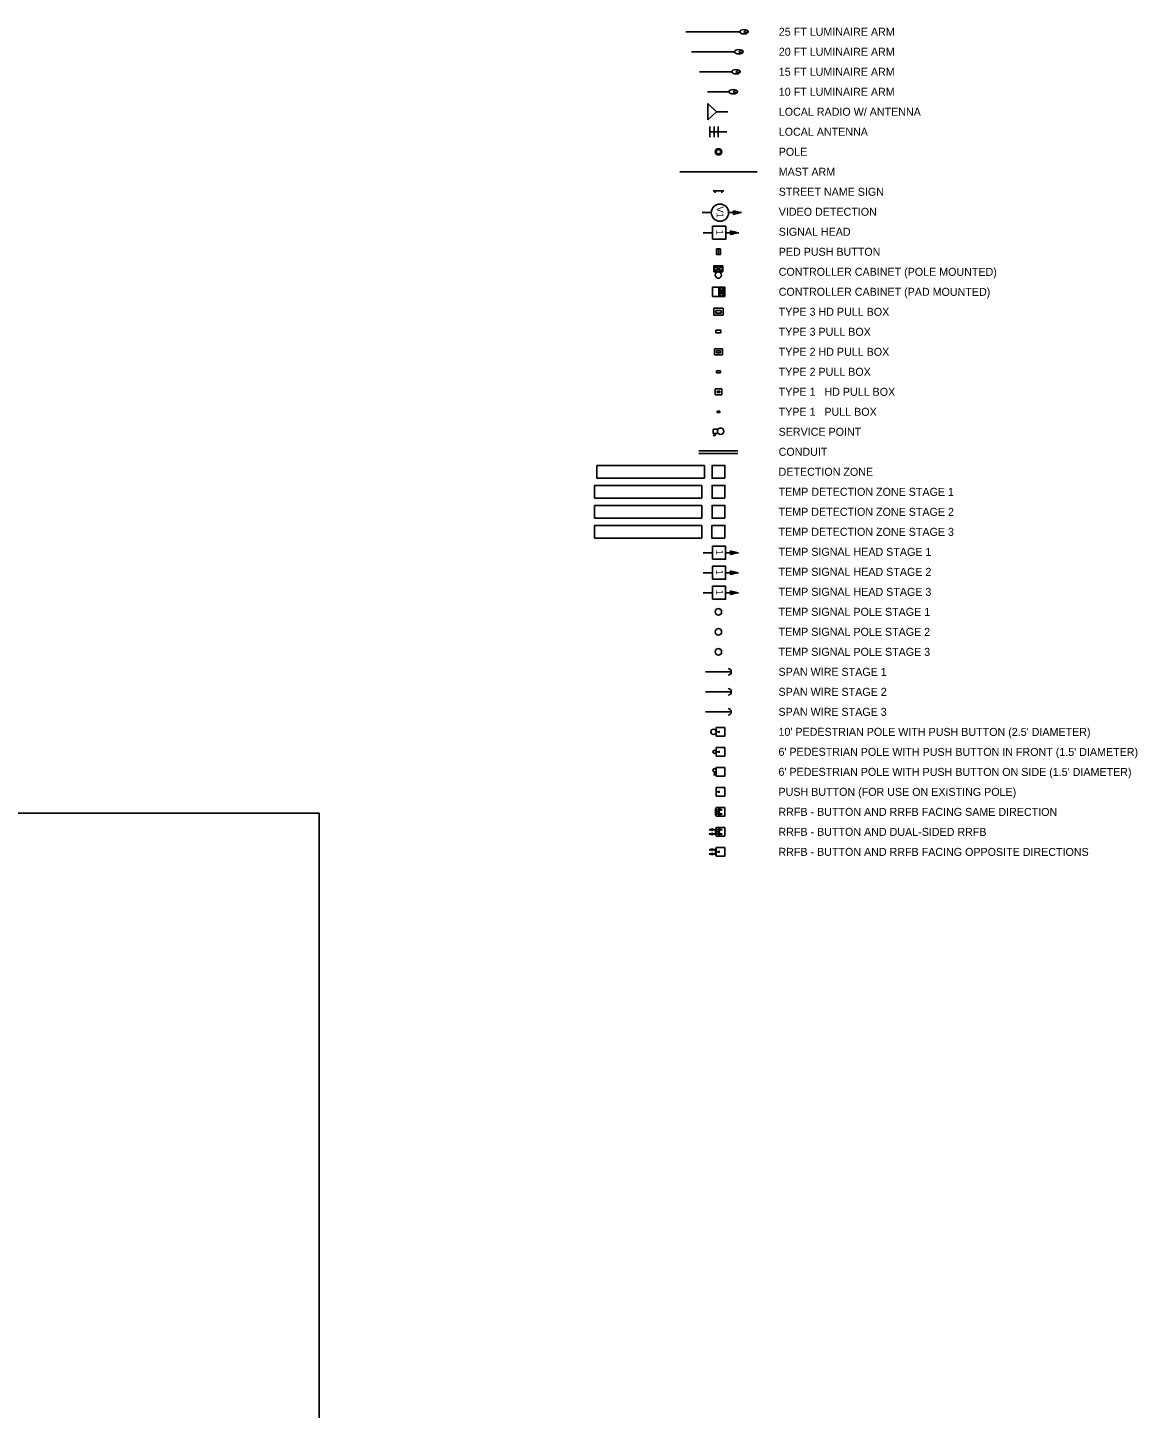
# Model space of a CAD drawing. Extents: x 991933 to 997296, y 1973751 to 1976728.
# Drawn here: x 993434 to 993950, y 1976002 to 1976644 of the extents above; entities that cross this region are included whole.
import ezdxf

# ---------------------------------------------------------------- set-up
doc = ezdxf.new("R2010")
doc.units = 0
for name, color, linetype in [('_CIVIL_CONSTRUCTION', 7, 'Continuous'), ('DSN_RDWY_Alignment Annotation', 7, 'Continuous'), ('DSN_ROW_Line-Annotation', 7, 'Continuous'), ('DSN_ROW_Point', 7, 'Continuous'), ('EX_ALIGNMENT', 7, 'Continuous'), ('EX_ROW', 7, 'Continuous'), ('EX_ROW_Annotation', 7, 'Continuous'), ('Level 23', 7, 'Continuous'), ('S_CROSS_DRAIN', 7, 'Continuous'), ('S_CURB', 7, 'Continuous'), ('S_DRIVEWAY', 7, 'Continuous'), ('S_DROP_INLET', 7, 'Continuous'), ('S_HWY_SYMBOLS', 7, 'Continuous'), ('S_HWY_TEXT', 7, 'Continuous'), ('S_ORTHO_IMAGE', 7, 'Continuous'), ('S_PARKING', 7, 'Continuous'), ('S_PAVEMENT_CROWN', 7, 'Continuous'), ('S_SHOULDER', 7, 'Continuous'), ('S_SIDEWALK', 7, 'Continuous'), ('S_WALL', 7, 'Continuous'), ('S_WALL_ANNOT', 7, 'Continuous')]:
    doc.layers.add(name, color=color, linetype=linetype)

msp = doc.modelspace()

# ---------------------------------------------------------------- linework, layer by layer
at = {"layer": '_CIVIL_CONSTRUCTION'}
for p, q in [((993697.45, 1976422.15), (993747.45, 1976422.15)), ((993697.45, 1976416.15), (993697.45, 1976422.15)), ((993747.45, 1976422.15), (993747.45, 1976416.15)), ((993747.45, 1976416.15), (993697.45, 1976416.15))]:
    msp.add_line(p, q, dxfattribs=at)
msp.add_lwpolyline([(993758.13, 1976416.15), (993752.13, 1976416.15), (993752.13, 1976422.15), (993758.13, 1976422.15)], close=True, dxfattribs=at)
at = {"layer": 'DSN_RDWY_Alignment Annotation'}
for p, q in [((993758.42, 1976400.1), (993764.46, 1976400.1)), ((993748.01, 1976400.08), (993752.35, 1976400.08))]:
    msp.add_line(p, q, dxfattribs=at)
msp.add_lwpolyline([(993752.35, 1976397.06), (993752.35, 1976403.12), (993758.42, 1976403.12), (993758.42, 1976397.06)], close=True, dxfattribs=at)
for centre, radius, start, end in [((993759.19, 1976400.1), 1.63, 328.15268, 31.84732), ((993768.87, 1976429.24), 29.47, 253.65357, 261.39168), ((993768.87, 1976370.96), 29.47, 98.60832, 106.34643)]:
    msp.add_arc(centre, radius, start, end, dxfattribs=at)
at = {"layer": 'DSN_ROW_Line-Annotation'}
msp.add_line((993761.08, 1976326.15), (993749.08, 1976326.15), dxfattribs=at)
msp.add_circle((993755.09, 1976354.05), 1.5, dxfattribs=at)
msp.add_arc((993759.58, 1976326.15), 1.5, 270, 90, dxfattribs=at)
at = {"layer": 'DSN_ROW_Point'}
for p, q in [((993748, 1976390.78), (993752.35, 1976390.78)), ((993758.41, 1976390.8), (993764.45, 1976390.8))]:
    msp.add_line(p, q, dxfattribs=at)
msp.add_lwpolyline([(993752.35, 1976387.76), (993752.35, 1976393.82), (993758.41, 1976393.82), (993758.41, 1976387.76)], close=True, dxfattribs=at)
for centre, radius, start, end in [((993759.19, 1976390.8), 1.63, 328.15268, 31.84732), ((993768.87, 1976419.94), 29.47, 253.65357, 261.39168), ((993768.87, 1976361.66), 29.47, 98.60832, 106.34643)]:
    msp.add_arc(centre, radius, start, end, dxfattribs=at)
at = {"layer": 'EX_ALIGNMENT'}
msp.add_line((993761.09, 1976335.45), (993749.09, 1976335.45), dxfattribs=at)
msp.add_circle((993755.1, 1976363.35), 1.5, dxfattribs=at)
msp.add_arc((993759.59, 1976335.45), 1.5, 270, 90, dxfattribs=at)
at = {"layer": 'EX_ROW'}
for p, q in [((993697.45, 1976412.85), (993747.45, 1976412.85)), ((993697.45, 1976406.85), (993697.45, 1976412.85)), ((993747.45, 1976406.85), (993697.45, 1976406.85)), ((993747.45, 1976412.85), (993747.45, 1976406.85))]:
    msp.add_line(p, q, dxfattribs=at)
msp.add_lwpolyline([(993758.12, 1976406.85), (993752.12, 1976406.85), (993752.12, 1976412.85), (993758.12, 1976412.85)], close=True, dxfattribs=at)
at = {"layer": 'EX_ROW_Annotation'}
for p, q in [((993748, 1976381.48), (993752.35, 1976381.48)), ((993758.41, 1976381.5), (993764.45, 1976381.5))]:
    msp.add_line(p, q, dxfattribs=at)
msp.add_lwpolyline([(993752.35, 1976378.46), (993752.35, 1976384.52), (993758.41, 1976384.52), (993758.41, 1976378.46)], close=True, dxfattribs=at)
for centre, radius, start, end in [((993759.18, 1976381.5), 1.63, 328.15268, 31.84732), ((993768.86, 1976410.64), 29.47, 253.65357, 261.39168), ((993768.86, 1976352.36), 29.47, 98.60832, 106.34643)]:
    msp.add_arc(centre, radius, start, end, dxfattribs=at)
at = {"layer": 'Level 23'}
msp.add_lwpolyline([(992579.43, 1975649.05), (993569.43, 1975649.05), (993569.43, 1976279.05), (992579.43, 1976279.05)], close=True, dxfattribs=at)
at = {"layer": 'S_CROSS_DRAIN'}
for p, q in [((993757.64, 1976568.45), (993752.64, 1976568.45)), ((993753.64, 1976567.45), (993753.64, 1976568.45)), ((993756.64, 1976568.45), (993756.64, 1976567.45)), ((993757.64, 1976568.45), (993756.64, 1976568.45))]:
    msp.add_line(p, q, dxfattribs=at)
at = {"layer": 'S_CURB'}
for p, q in [((993737.14, 1976577.25), (993773.14, 1976577.25)), ((993753.82, 1976281.15), (993753.82, 1976278.15)), ((993753.82, 1976280.65), (993756.84, 1976280.65)), ((993753.82, 1976279.77), (993753.82, 1976279.52)), ((993753.82, 1976279.77), (993754.07, 1976279.77)), ((993754.07, 1976279.52), (993753.82, 1976279.52)), ((993753.82, 1976278.65), (993756.84, 1976278.65)), ((993754.07, 1976279.52), (993754.07, 1976279.77)), ((993753.81, 1976271.85), (993753.81, 1976268.85)), ((993753.81, 1976271.35), (993750.79, 1976271.35)), ((993753.81, 1976269.35), (993750.79, 1976269.35)), ((993753.81, 1976271.35), (993756.83, 1976271.35)), ((993753.81, 1976270.47), (993753.81, 1976270.22)), ((993753.81, 1976270.47), (993754.06, 1976270.47)), ((993754.06, 1976270.22), (993753.81, 1976270.22)), ((993753.81, 1976269.35), (993756.83, 1976269.35)), ((993754.06, 1976270.22), (993754.06, 1976270.47)), ((993753.81, 1976262.05), (993750.79, 1976262.05)), ((993753.81, 1976260.05), (993750.79, 1976260.05)), ((993753.81, 1976262.55), (993753.81, 1976259.55)), ((993753.81, 1976261.17), (993753.81, 1976260.92)), ((993753.81, 1976261.17), (993754.06, 1976261.17)), ((993754.06, 1976260.92), (993753.81, 1976260.92)), ((993754.06, 1976260.92), (993754.06, 1976261.17))]:
    msp.add_line(p, q, dxfattribs=at)
for centre, radius in [((993755.14, 1976586.55), 1.5), ((993755.14, 1976586.55), 1.25), ((993755.14, 1976586.55), 1), ((993755.1, 1976372.65), 1.5), ((993752.83, 1976316.85), 1.25), ((993753.33, 1976307.55), 0.75), ((993753.33, 1976299), 0.75)]:
    msp.add_circle(centre, radius, dxfattribs=at)
for centre, radius, start, end in [((993754.2, 1976280.65), 0.814, 328.15268, 31.84732), ((993759.04, 1976295.22), 14.74, 253.65357, 261.39168), ((993759.04, 1976266.08), 14.74, 98.60832, 106.34643), ((993754.2, 1976278.65), 0.814, 328.15268, 31.84732), ((993759.04, 1976293.22), 14.74, 253.65357, 261.39168), ((993759.04, 1976264.08), 14.74, 98.60832, 106.34643), ((993748.59, 1976285.92), 14.74, 278.60832, 286.34643), ((993753.43, 1976271.35), 0.814, 148.15268, 211.84732), ((993754.2, 1976271.35), 0.814, 328.15268, 31.84732), ((993759.04, 1976285.92), 14.74, 253.65357, 261.39168), ((993748.59, 1976256.78), 14.74, 73.65357, 81.39168), ((993748.59, 1976283.92), 14.74, 278.60832, 286.34643), ((993748.59, 1976254.78), 14.74, 73.65357, 81.39168), ((993753.43, 1976269.35), 0.814, 148.15268, 211.84732), ((993759.04, 1976256.78), 14.74, 98.60832, 106.34643), ((993754.2, 1976269.35), 0.814, 328.15268, 31.84732), ((993759.04, 1976283.92), 14.74, 253.65357, 261.39168), ((993759.04, 1976254.78), 14.74, 98.60832, 106.34643), ((993748.58, 1976276.62), 14.74, 278.60832, 286.34643), ((993748.58, 1976247.48), 14.74, 73.65357, 81.39168), ((993748.58, 1976274.62), 14.74, 278.60832, 286.34643), ((993748.58, 1976245.48), 14.74, 73.65357, 81.39168), ((993753.42, 1976262.05), 0.814, 148.15268, 211.84732), ((993753.42, 1976260.05), 0.814, 148.15268, 211.84732)]:
    msp.add_arc(centre, radius, start, end, dxfattribs=at)
at = {"layer": 'S_DRIVEWAY'}
for p, q in [((993757.31, 1976513.78), (993752.98, 1976513.78)), ((993752.98, 1976513.78), (993752.98, 1976510.51)), ((993752.98, 1976510.51), (993757.31, 1976510.51)), ((993753.98, 1976512.78), (993753.98, 1976511.51)), ((993756.31, 1976512.78), (993753.98, 1976512.78)), ((993753.98, 1976511.51), (993756.31, 1976511.51)), ((993756.31, 1976511.51), (993756.31, 1976512.78)), ((993757.31, 1976510.51), (993757.31, 1976513.78)), ((993753.97, 1976503.66), (993753.97, 1976502.39)), ((993756.3, 1976503.66), (993753.97, 1976503.66)), ((993756.3, 1976502.39), (993756.3, 1976503.66)), ((993753.97, 1976502.39), (993756.3, 1976502.39)), ((993757.01, 1976495), (993753.26, 1976495)), ((993753.26, 1976495), (993753.26, 1976492.08)), ((993753.26, 1976492.08), (993757.01, 1976492.08)), ((993754.26, 1976493.08), (993754.26, 1976494)), ((993754.26, 1976494), (993756.01, 1976494)), ((993754.26, 1976494), (993754.26, 1976493.08)), ((993756.01, 1976494), (993754.26, 1976494)), ((993754.26, 1976493.08), (993756.01, 1976493.08)), ((993754.26, 1976493.08), (993756.01, 1976493.08)), ((993756.01, 1976493.08), (993756.01, 1976494)), ((993756.01, 1976493.08), (993756.01, 1976494)), ((993757.01, 1976492.08), (993757.01, 1976495)), ((993754.26, 1976484.71), (993754.26, 1976483.79)), ((993756.01, 1976484.71), (993754.26, 1976484.71)), ((993754.26, 1976483.79), (993756.01, 1976483.79)), ((993756.01, 1976483.79), (993756.01, 1976484.71)), ((993754.08, 1976316.85), (993755.4, 1976316.85)), ((993755.4, 1976316.41), (993755.4, 1976317.28)), ((993754.08, 1976307.55), (993755.4, 1976307.55)), ((993755.4, 1976307.11), (993755.4, 1976307.98)), ((993753.33, 1976298.25), (993753.33, 1976296.93)), ((993752.89, 1976296.93), (993753.76, 1976296.93)), ((993754.07, 1976288.95), (993755.39, 1976288.95)), ((993755.39, 1976288.51), (993755.39, 1976289.38)), ((993754.07, 1976279.65), (993755.39, 1976279.65)), ((993755.38, 1976279.21), (993755.39, 1976280.08)), ((993754.06, 1976270.35), (993755.38, 1976270.35)), ((993755.38, 1976269.91), (993755.38, 1976270.78)), ((993754.06, 1976261.05), (993755.38, 1976261.05)), ((993755.38, 1976260.61), (993755.38, 1976261.48))]:
    msp.add_line(p, q, dxfattribs=at)
msp.add_lwpolyline([(993754.28, 1976538.73), (993756.02, 1976538.73), (993756.02, 1976541.36), (993754.28, 1976541.36)], close=True, dxfattribs=at)
at = {"layer": 'S_DROP_INLET'}
for points in [[(993754.08, 1976318.85), (993758.08, 1976318.85), (993758.08, 1976314.85), (993754.08, 1976314.85)], [(993754.08, 1976309.55), (993758.08, 1976309.55), (993758.08, 1976305.55), (993754.08, 1976305.55)], [(993754.08, 1976300.25), (993758.08, 1976300.25), (993758.08, 1976296.25), (993754.08, 1976296.25)], [(993754.07, 1976290.95), (993758.07, 1976290.95), (993758.07, 1976286.95), (993754.07, 1976286.95)], [(993754.07, 1976281.65), (993758.07, 1976281.65), (993758.07, 1976277.65), (993754.07, 1976277.65)], [(993754.06, 1976272.35), (993758.06, 1976272.35), (993758.06, 1976268.35), (993754.06, 1976268.35)], [(993754.06, 1976263.05), (993758.06, 1976263.05), (993758.06, 1976259.05), (993754.06, 1976259.05)]]:
    msp.add_lwpolyline(points, close=True, dxfattribs=at)
at = {"layer": 'S_HWY_SYMBOLS'}
for p, q in [((993697.46, 1976431.45), (993747.46, 1976431.45)), ((993697.46, 1976425.45), (993697.46, 1976431.45)), ((993747.46, 1976431.45), (993747.46, 1976425.45)), ((993747.46, 1976425.45), (993697.46, 1976425.45))]:
    msp.add_line(p, q, dxfattribs=at)
msp.add_lwpolyline([(993758.13, 1976425.45), (993752.13, 1976425.45), (993752.13, 1976431.45), (993758.13, 1976431.45)], close=True, dxfattribs=at)
at = {"layer": 'S_HWY_TEXT'}
msp.add_line((993761.09, 1976344.75), (993749.09, 1976344.75), dxfattribs=at)
msp.add_arc((993759.59, 1976344.75), 1.5, 270, 90, dxfattribs=at)
at = {"layer": 'S_PARKING'}
for p, q in [((993752.63, 1976457.6), (993752.63, 1976455.6)), ((993752.63, 1976457.6), (993754.63, 1976457.6)), ((993752.63, 1976455.6), (993754.63, 1976455.6)), ((993752.63, 1976454.6), (993753.63, 1976454.6)), ((993753.63, 1976455.6), (993753.63, 1976454.6)), ((993754.63, 1976457.6), (993754.63, 1976455.6)), ((993746.06, 1976447.54), (993764.19, 1976447.54)), ((993746.06, 1976446.22), (993764.19, 1976446.22))]:
    msp.add_line(p, q, dxfattribs=at)
msp.add_circle((993756.13, 1976456.6), 1.5, dxfattribs=at)
at = {"layer": 'S_PAVEMENT_CROWN'}
for p, q in [((993752.28, 1976523.61), (993758.02, 1976523.61)), ((993752.28, 1976523.61), (993752.28, 1976519.28)), ((993755.28, 1976523.61), (993755.28, 1976519.28)), ((993755.61, 1976523.28), (993755.61, 1976519.61)), ((993757.69, 1976519.61), (993755.61, 1976523.28)), ((993755.61, 1976523.28), (993757.69, 1976523.28)), ((993757.69, 1976523.26), (993755.61, 1976519.61)), ((993757.69, 1976523.28), (993757.69, 1976519.61)), ((993758.02, 1976523.61), (993758.02, 1976519.28)), ((993752.28, 1976519.28), (993758.02, 1976519.28)), ((993755.61, 1976519.61), (993757.69, 1976519.61))]:
    msp.add_line(p, q, dxfattribs=at)
at = {"layer": 'S_SHOULDER'}
for p, q in [((993740, 1976642.34), (993765, 1976642.34)), ((993742.59, 1976633.04), (993762.59, 1976633.04)), ((993746.29, 1976623.74), (993761.29, 1976623.74)), ((993750.02, 1976614.44), (993760.02, 1976614.44)), ((993750.14, 1976601.43), (993750.14, 1976608.93)), ((993750.14, 1976608.93), (993754.14, 1976605.18)), ((993754.14, 1976605.18), (993750.14, 1976601.43)), ((993759.49, 1976605.18), (993754.14, 1976605.18)), ((993751.06, 1976598.34), (993751.06, 1976593.34)), ((993751.06, 1976595.84), (993759.06, 1976595.84)), ((993753.06, 1976598.34), (993753.06, 1976593.34)), ((993755.06, 1976598.34), (993755.06, 1976593.34)), ((993752.9, 1976530.73), (993752.9, 1976533.47)), ((993752.9, 1976533.47), (993757.23, 1976533.47)), ((993752.9, 1976530.73), (993757.23, 1976530.73)), ((993753.23, 1976533.14), (993756.9, 1976533.14)), ((993753.23, 1976531.06), (993753.23, 1976533.14)), ((993756.9, 1976533.14), (993753.23, 1976531.06)), ((993753.23, 1976531.06), (993756.9, 1976531.06)), ((993753.25, 1976533.14), (993756.9, 1976531.06)), ((993756.9, 1976531.06), (993756.9, 1976533.14)), ((993757.23, 1976530.73), (993757.23, 1976533.47)), ((993753.54, 1976476.31), (993756.73, 1976476.31)), ((993753.54, 1976473.58), (993753.54, 1976476.31)), ((993753.54, 1976473.58), (993756.73, 1976473.58)), ((993754.54, 1976474.58), (993754.54, 1976475.31)), ((993754.54, 1976475.31), (993755.73, 1976475.31)), ((993754.54, 1976474.58), (993755.73, 1976474.58)), ((993755.73, 1976474.58), (993755.73, 1976475.31)), ((993756.73, 1976473.58), (993756.73, 1976476.31)), ((993754.54, 1976465.28), (993754.54, 1976466.01)), ((993754.54, 1976466.01), (993755.73, 1976466.01)), ((993754.54, 1976465.28), (993755.73, 1976465.28)), ((993755.73, 1976465.28), (993755.73, 1976466.01))]:
    msp.add_line(p, q, dxfattribs=at)
msp.add_circle((993755.06, 1976529.23), 1.5, dxfattribs=at)
for centre, major_axis in [((993767, 1976642.34), (2, 0)), ((993768, 1976642.34), (-1, 0)), ((993764.59, 1976633.04), (2, 0)), ((993765.59, 1976633.04), (-1, 0)), ((993763.29, 1976623.74), (2, 0)), ((993764.29, 1976623.74), (-1, 0)), ((993762.02, 1976614.44), (2, 0)), ((993763.02, 1976614.44), (-1, 0))]:
    msp.add_ellipse(centre, major_axis=major_axis, ratio=0.5, dxfattribs=at)
at = {"layer": 'S_SIDEWALK'}
for p, q in [((993747.48, 1976558.26), (993751.81, 1976558.26)), ((993759.81, 1976558.26), (993765.88, 1976558.26)), ((993748.07, 1976548.88), (993752.42, 1976548.88)), ((993758.48, 1976548.9), (993764.52, 1976548.9))]:
    msp.add_line(p, q, dxfattribs=at)
msp.add_lwpolyline([(993752.42, 1976545.86), (993752.42, 1976551.92), (993758.48, 1976551.92), (993758.48, 1976545.86)], close=True, dxfattribs=at)
msp.add_circle((993755.81, 1976558.26), 4, dxfattribs=at)
for centre, radius, start, end in [((993760.61, 1976558.26), 1.63, 328.15268, 31.84732), ((993770.29, 1976587.4), 29.47, 253.65357, 261.39168), ((993770.29, 1976529.12), 29.47, 98.60832, 106.34643), ((993759.26, 1976548.9), 1.63, 328.15268, 31.84732), ((993768.93, 1976578.04), 29.47, 253.65357, 261.39168), ((993768.93, 1976519.76), 29.47, 98.60832, 106.34643)]:
    msp.add_arc(centre, radius, start, end, dxfattribs=at)
at = {"layer": 'S_WALL'}
for p, q in [((993698.62, 1976440.75), (993748.62, 1976440.75)), ((993698.62, 1976434.75), (993698.62, 1976440.75)), ((993748.62, 1976440.75), (993748.62, 1976434.75)), ((993748.62, 1976434.75), (993698.62, 1976434.75))]:
    msp.add_line(p, q, dxfattribs=at)
msp.add_lwpolyline([(993758.14, 1976434.75), (993752.14, 1976434.75), (993752.14, 1976440.75), (993758.14, 1976440.75)], close=True, dxfattribs=at)
at = {"layer": 'S_WALL_ANNOT'}
msp.add_lwpolyline([(993754.28, 1976541.36), (993754.28, 1976538.73), (993755.15, 1976538.73), (993755.15, 1976541.36)], close=True, dxfattribs=at)

# ---------------------------------------------------------------- texts
at = {"layer": 'DSN_RDWY_Alignment Annotation'}
msp.add_text('1', height=3.25, rotation=270, dxfattribs=at).set_placement((993754.01, 1976401.56))
at = {"layer": 'DSN_ROW_Point'}
msp.add_text('1', height=3.25, rotation=270, dxfattribs=at).set_placement((993754, 1976392.26))
at = {"layer": 'EX_ROW_Annotation'}
msp.add_text('1', height=3.25, rotation=270, dxfattribs=at).set_placement((993754, 1976382.96))
at = {"layer": 'S_ORTHO_IMAGE'}
for s, p in [('25 FT LUMINAIRE ARM', (993783.18, 1976640.5)), ('20 FT LUMINAIRE ARM', (993783.18, 1976631.2)), ('15 FT LUMINAIRE ARM', (993783.17, 1976621.9)), ('10 FT LUMINAIRE ARM', (993783.17, 1976612.6)), ('LOCAL RADIO W/ ANTENNA', (993783.17, 1976603.3)), ('LOCAL ANTENNA', (993783.16, 1976594)), ('POLE', (993783.16, 1976584.7)), ('MAST ARM', (993783.15, 1976575.4)), ('STREET NAME SIGN', (993783.15, 1976566.1)), ('VIDEO DETECTION', (993783.15, 1976556.8)), ('SIGNAL HEAD', (993783.14, 1976547.5)), ('PED PUSH BUTTON', (993783.14, 1976538.2)), ('CONTROLLER CABINET (POLE MOUNTED)', (993783.13, 1976528.9)), ('CONTROLLER CABINET (PAD MOUNTED)', (993783.13, 1976519.6)), ('TYPE 3 HD PULL BOX', (993783.12, 1976510.3)), ('TYPE 3 PULL BOX', (993783.12, 1976501)), ('TYPE 2 HD PULL BOX', (993783.12, 1976491.7)), ('TYPE 2 PULL BOX', (993783.11, 1976482.4)), ('TYPE 1   HD PULL BOX', (993783.11, 1976473.1)), ('TYPE 1   PULL BOX', (993783.1, 1976463.8)), ('SERVICE POINT', (993783.1, 1976454.5)), ('CONDUIT', (993783.1, 1976445.2)), ('DETECTION ZONE', (993783.09, 1976435.9)), ('TEMP DETECTION ZONE STAGE 1', (993783.09, 1976426.6)), ('TEMP DETECTION ZONE STAGE 2', (993783.08, 1976417.3)), ('TEMP DETECTION ZONE STAGE 3', (993783.08, 1976408)), ('TEMP SIGNAL HEAD STAGE 1', (993783.08, 1976398.7)), ('TEMP SIGNAL HEAD STAGE 2', (993783.07, 1976389.4)), ('TEMP SIGNAL HEAD STAGE 3', (993783.07, 1976380.1)), ('TEMP SIGNAL POLE STAGE 1', (993783.06, 1976370.8)), ('TEMP SIGNAL POLE STAGE 2', (993783.06, 1976361.5)), ('TEMP SIGNAL POLE STAGE 3', (993783.06, 1976352.2)), ('SPAN WIRE STAGE 1', (993783.05, 1976342.9)), ('SPAN WIRE STAGE 2', (993783.05, 1976333.6)), ('SPAN WIRE STAGE 3', (993783.04, 1976324.3)), ("10' PEDESTRIAN POLE WITH PUSH BUTTON (2.5' DIAMETER)", (993783.04, 1976315)), ("6' PEDESTRIAN POLE WITH PUSH BUTTON IN FRONT (1.5' DIAMETER)", (993783.04, 1976305.7)), ("6' PEDESTRIAN POLE WITH PUSH BUTTON ON SIDE (1.5' DIAMETER)", (993783.03, 1976296.4)), ('PUSH BUTTON (FOR USE ON EXISTING POLE)', (993783.03, 1976287.1)), ('RRFB - BUTTON AND RRFB FACING SAME DIRECTION', (993783.02, 1976277.8)), ('RRFB - BUTTON AND DUAL-SIDED RRFB', (993783.02, 1976268.5)), ('RRFB - BUTTON AND RRFB FACING OPPOSITE DIRECTIONS', (993783.01, 1976259.2))]:
    msp.add_text(s, height=3.72, rotation=359.97484, dxfattribs=at).set_placement(p)
at = {"layer": 'S_SIDEWALK'}
for s, p in [('V1', (993754.22, 1976561.14)), ('1', (993754.07, 1976550.36))]:
    msp.add_text(s, height=3.25, rotation=270, dxfattribs=at).set_placement(p)

doc.saveas('drawing.dxf')
